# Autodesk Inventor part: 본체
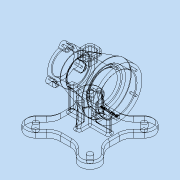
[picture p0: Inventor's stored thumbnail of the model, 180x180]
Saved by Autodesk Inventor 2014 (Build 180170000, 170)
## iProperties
Created: 2018-03
Part Number: 본체
Material: Generic
Document SubType Name: Modeling
Designer: kb542
Density: 1 g/cm^3
Appearance: Default
Author: kb542
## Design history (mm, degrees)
sketch "스케치1"
  geometry: L1 (-45, -45)-(45, -45); L2 (45, -45)-(45, 45); L3 (45, 45)-(-45, 45); L4 (-45, 45)-(-45, -45); L5 (-45, -45)-(45, 45); L6 (45, -45)-(-45, 45); 1 further point
  constraints: 12 end point, 2 midpoint, 2 parallel, 1 horizontal, 1 perpendicular
  dimensions: "d0" = 90 distance of L2.end L3.end; "d1" = 90 distance of L1.end L2.end
extrude "돌출1" new body sketch "스케치1" distance "d2" = 12; taper "d3" = 0 deg
sketch "스케치2"
  geometry: L1 (-45, 45)-(-45, -45) reference; L2 (-45, -45)-(45, -45) reference; L3 (0, 0)-(-59.607, -59.607); L4 (0, 0)-(-45, 0); L5 (-62.225, -36.77)-(-41.012, -15.556); L6 (-36.77, -62.225)-(-15.556, -41.012); L7 (-15.556, -41.012)-(-41.012, -15.556); A1 r 70 centre (0, 0) between (-49.497, -49.497) and (-60.483, -35.239); A2 r 18 centre (-49.497, -49.497) between (-60.483, -35.239) and (-36.77, -62.225); 1 further point
  constraints: 10 end point, 5 point on circle, 2 centre point, 2 symmetric about line, 1 coincident, 1 midpoint, 1 parallel, 1 perpendicular, 1 point on line, 1 tangent
  dimensions: "d4" = 140 diameter of A1; "d5" = 45 deg angle of L4 L3; "d6" = 36 diameter of A2; "d8" = 40 distance from line of point (0, 0) L7
extrude "돌출2" join sketch "스케치2" distance "d9" = 12; taper "d10" = 0 deg
sketch "스케치3"
  geometry: L1 (-19.544, 0)-(19.544, 0) reference; L2 (-67.497, 12)-(-67.497, 0) reference; L3 (-30, 82)-(-30, 127); L4 (-30, 127)-(-50, 127); L5 (-50, 127)-(-50, 82); L6 (-50, 82)-(50, 82); L7 (50, 109.5)-(50, 82); L8 (67.497, 0)-(36.77, 0) reference; L9 (50, 109.5)-(27, 109.5); L10 (27, 109.5)-(-30, 127); 6 further points
  constraints: 14 end point, 4 midpoint, 2 parallel, 1 horizontal, 1 perpendicular, 1 point on line, 1 vertical alignment
  dimensions: "d24" = 20 distance of L3.end L4.end; "d26" = 82 distance from line of L8 L6.end; "d27" = 100 distance between parallel lines of L7 L5; "d30" = 90 diameter of L4 L6; "d42" = 77 distance from line of L5 L9.end; "d43" = 55 diameter of L9 L6
revolve "회전1" sketch "스케치3" stored, may be unused: angle "d34" = 90 deg
sketch "스케치4"
  geometry: L1 (-50, 37)-(-50, 127) reference; L2 (-50, 82)-(-27, 82); L3 (-27, 82)-(-27, 117); L4 (-27, 117)-(-50, 117); L5 (-50, 117)-(-50, 82); L6 (-27, 82)-(20, 82); L7 (20, 82)-(20, 108); L8 (20, 108)-(-27, 108); L9 (-27, 108)-(-27, 82); L10 (20, 82)-(50, 82); L11 (50, 82)-(50, 102); L12 (50, 102)-(20, 102); L13 (20, 102)-(20, 82); L14 (50, 54.5)-(50, 109.5) reference; 1 further point
  constraints: 24 end point, 6 parallel, 3 horizontal, 3 perpendicular, 1 midpoint
  dimensions: "d35" = 23 distance of L3.end L4.end; "d36" = 30 distance of L11.end L12.end; "d37" = 47 distance of L7.end L8.end; "d38" = 52 diameter of L8 L6; "d39" = 70 diameter of L4 L2; "d41" = 40 diameter of L12 L10
revolve "회전2" sketch "스케치4" stored, may be unused: angle "d44" = 90 deg
sketch "스케치5"
  geometry: L1 (4, 24)-(-4, 24); L2 (-4, 24)-(-4, -24); L3 (-4, -24)-(4, -24); L4 (4, -24)-(4, 24); L5 (4, 24)-(-4, -24); L6 (-4, 24)-(4, -24); L7 (37, 4)-(-37, 4); L8 (-37, 4)-(-37, -4); L9 (-37, -4)-(37, -4); L10 (37, -4)-(37, 4); L11 (37, 4)-(-37, -4); L12 (-37, 4)-(37, -4); 1 further point
  constraints: 24 end point, 4 midpoint, 4 parallel, 2 horizontal, 2 perpendicular
  dimensions: "d45" = 48 distance of L1.end L2.end; "d46" = 8 distance of L2.end L3.end; "d47" = 8 distance of L9.end L7.start; "d48" = 74 distance of L8.end L9.end
extrude "돌출3" join sketch "스케치5" stored distance "d49" = 12; taper "d50" = 0 deg
extrude "돌출4" join sketch "스케치5" stored distance "d51" = 12; taper "d52" = 0 deg
feature "면 기울기1" dims angle "d53" = 5 deg
node "작업 평면1"
sketch "스케치6"
  geometry: L1 (-12.5, 12.5)-(12.5, 12.5); L2 (12.5, 12.5)-(12.5, -12.5); L3 (12.5, -12.5)-(-12.5, -12.5); L4 (-12.5, -12.5)-(-12.5, 12.5); L5 (-12.5, 12.5)-(12.5, -12.5); L6 (12.5, 12.5)-(-12.5, -12.5); L7 (-7.5, 7.5)-(7.5, 7.5); L8 (7.5, 7.5)-(7.5, -7.5); L9 (7.5, -7.5)-(-7.5, -7.5); L10 (-7.5, -7.5)-(-7.5, 7.5); L11 (-7.5, 7.5)-(7.5, -7.5); L12 (7.5, 7.5)-(-7.5, -7.5); 1 further point
  constraints: 24 end point, 4 midpoint, 4 parallel, 2 horizontal, 2 perpendicular, 1 point on line
  dimensions: "d55" = 25 distance of L2.end L3.end; "d56" = 25 distance of L3.end L1.start (= d55); "d57" = 15 distance of L8.end L9.end
extrude "돌출5" join sketch "스케치6" stored distance "d58" = 12; taper "d59" = 0 deg
extrude "돌출6" cut sketch "스케치6" stored distance "d60" = 12; taper "d61" = 0 deg
sketch "스케치7"
  geometry: A1 r 18 centre (-49.497, 49.497) between (-36.77, 62.225) and (-62.225, 36.77) reference; A2 r 18 centre (-49.497, -49.497) between (-62.225, -36.77) and (-36.77, -62.225) reference; A3 r 18 centre (49.497, -49.497) between (36.77, -62.225) and (62.225, -36.77) reference; A4 r 18 centre (49.497, 49.497) between (62.225, 36.77) and (36.77, 62.225) reference; 1 further point
hole "구멍1" sketch "스케치7" at (-49.497, 49.497), (49.497, 49.497), (49.497, -49.497), (-49.497, -49.497) diameter "d62" = 10; stored, may be unused: countersink angle "d66" = 90 deg, drill point angle "d68" = 118 deg; dims "d63" = 6, "d64" = 4, "d65" = 2, "d67" = 8
fillet "모깎기1" dims "d69" = 25
chamfer "모따기1" distance "d70" = 3; stored, may be unused: second distance "d71" = 2, angle "d72" = 45 deg
fillet "모깎기2" dims "d73" = 8
fillet "모깎기3" dims "d74" = 1
fillet "모깎기4" dims "d75" = 3
fillet "모깎기5" dims "d76" = 3
chamfer "모따기2" distance "d77" = 1; stored, may be unused: second distance "d78" = 2, angle "d79" = 45 deg
sketch "스케치8"
  geometry: C1 r 20 at (0, 0) reference; C2 r 7 at (27.5, 0); 2 further points
  constraints: 2 horizontal alignment, 1 centre point, 1 other
  dimensions: "d80" = 14 diameter of C2
extrude "돌출7" join sketch "스케치8" distance "d81" = 15; taper "d82" = 0 deg
fillet "모깎기6" dims "d83" = 3
fillet "모깎기7" dims "d84" = 1
sketch "스케치9"
  geometry: A1 r 7 centre (-41.25, -23.816) between (-47.248, -20.206) and (-35.125, -27.205) reference; A2 r 7 centre (0, 0) between (-0.127, -6.999) and (-0.127, 6.999) reference; A3 r 7 centre (-41.25, 23.816) between (-35.125, 27.205) and (-47.248, 20.206) reference; 1 further point
hole "구멍2" sketch "스케치9" at (0, 0), (-41.25, 23.816), (-41.25, -23.816) diameter "d88" = 3.242; stored, may be unused: countersink angle "d92" = 90 deg, drill point angle "d94" = 118 deg; dims "d89" = 9, "d90" = 4, "d91" = 2, "d93" = 11
fillet "모깎기8" dims "d95" = 3
fillet "모깎기9" dims "d96" = 3
sketch "스케치10" dims "d97" = 80
  geometry: C1 r 35 at (0, 0) reference; C2 r 45 at (0, 0) reference; 3 further points
  constraints: 2 horizontal alignment, 1 coincident, 2 other
hole "구멍3" sketch "스케치10" at (-40, 0) diameter "d98" = 3.242; stored, may be unused: countersink angle "d102" = 90 deg, drill point angle "d104" = 118 deg; dims "d99" = 9, "d100" = 4, "d101" = 2, "d103" = 11
node "작업 평면2"
sketch "스케치11"
  geometry: L1 (45, -9.189)-(45, 9.189) reference; 2 further points
  constraints: 1 other
  dimensions: "d115" = 45 distance from line of L1 point (0, 35); "d116" = 35 distance of point (0, 0) point (0, 35)
feature "엠보싱1" sketch "스케치11" dims "d9" = 12, "d109" = 0.5, "d110" = 0
fillet "모깎기10" dims "d111" = 3
chamfer "모따기3" distance "d112" = 1; stored, may be unused: second distance "d113" = 2, angle "d114" = 45 deg
node "솔리드1"
mirror "대칭1"
mirror "대칭2"
pattern_circular "원형 패턴1" dims "d86" = 360 deg
pattern_circular "원형 패턴2" dims angle "d106" = 360 deg
other parameters: "d54" = -127, "d108" = 5
